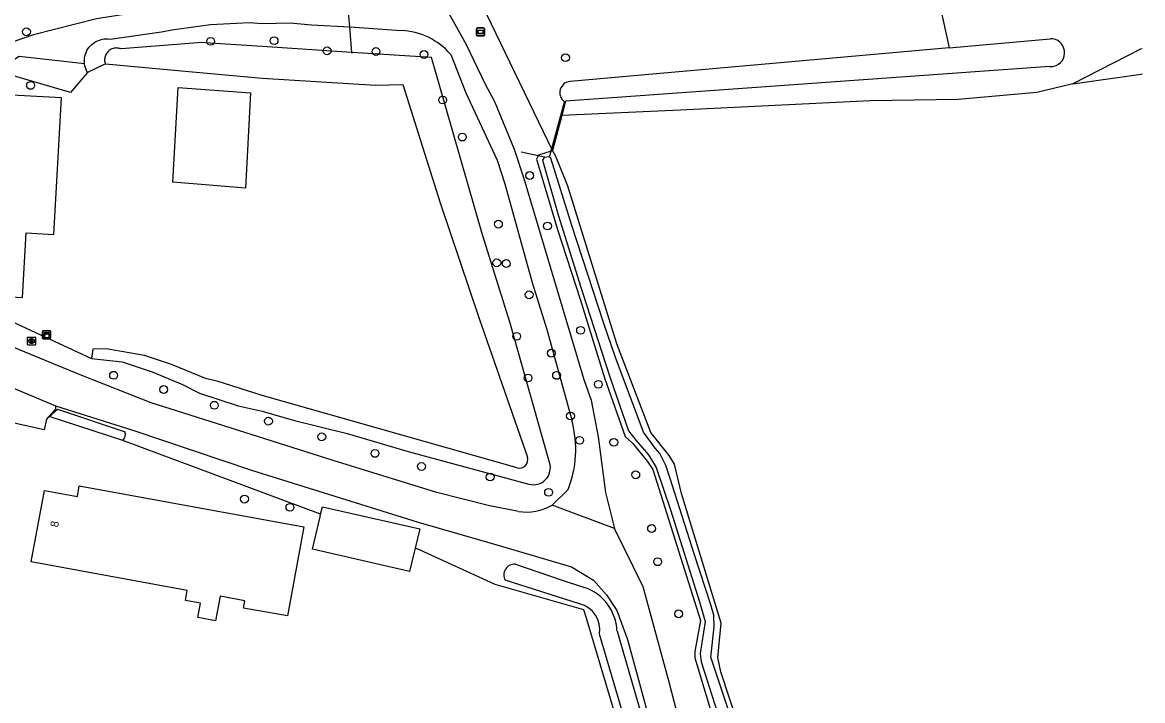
# Model space of a CAD drawing. Extents: x 163863 to 164644, y 379566 to 382155.
# Drawn here: x 164470.1 to 164610, y 381253.7 to 381338.5 of the extents above; entities that cross this region are included whole.
import ezdxf

# ---------------------------------------------------------------- set-up
doc = ezdxf.new("R2010")
doc.units = 0
for name, color, linetype in [('IMGEO_Boom', 7, 'Continuous'), ('IMGEO_Duiker', 7, 'Continuous'), ('IMGEO_Grasland_agrarisch', 7, 'Continuous'), ('IMGEO_Grasland_overig', 7, 'Continuous'), ('IMGEO_Groenvoorziening', 7, 'Continuous'), ('IMGEO_Houtwal', 7, 'Continuous'), ('IMGEO_Kast', 7, 'Continuous'), ('IMGEO_Pand', 7, 'Continuous'), ('IMGEO_Pand_nummerreeks', 7, 'Continuous'), ('IMGEO_Rijbaan_lokaal_onverhard', 7, 'Continuous'), ('IMGEO_Rijbaan_lokaal_open', 7, 'Continuous'), ('IMGEO_Rioolput', 7, 'Continuous'), ('IMGEO_Sloot', 7, 'Continuous'), ('IMGEO_Verklikker', 7, 'Continuous'), ('IMGEO_Waterloop', 7, 'Continuous')]:
    doc.layers.add(name, color=color, linetype=linetype)

msp = doc.modelspace()

# ---------------------------------------------------------------- linework, layer by layer
at = {"layer": 'IMGEO_Boom'}
for centre in [(164470.56, 381337.3), (164493.58, 381336.1), (164501.5, 381336.19), (164508.13, 381334.92), (164514.23, 381334.83), (164520.24, 381334.47), (164537.91, 381334.06), (164471.08, 381330.6), (164522.56, 381328.77), (164525.03, 381324.14), (164533.43, 381319.34), (164529.53, 381313.26), (164535.67, 381313.03), (164529.33, 381308.42), (164530.51, 381308.33), (164533.37, 381304.43), (164539.8, 381299.98), (164531.81, 381299.24), (164536.15, 381297.13), (164481.45, 381294.37), (164536.8, 381294.35), (164533.23, 381294.02), (164542.02, 381293.24), (164487.7, 381292.59), (164494.03, 381290.62), (164500.8, 381288.63), (164538.54, 381289.27), (164507.46, 381286.68), (164539.69, 381286.24), (164543.95, 381285.98), (164514.11, 381284.6), (164519.92, 381282.97), (164528.5, 381281.65), (164546.69, 381281.93), (164497.8, 381278.89), (164535.8, 381279.73), (164503.48, 381277.86), (164548.67, 381275.21), (164549.43, 381271.06), (164552.05, 381264.55)]:
    msp.add_circle(centre, 0.489, dxfattribs=at)
at = {"layer": 'IMGEO_Duiker'}
for points in [[(164511.24, 381334.6), (164511.23, 381334.72), (164510.95, 381337.93), (164510.59, 381341.96), (164510.51, 381342.79), (164510.45, 381343.54), (164510.38, 381344.3)], [(164535.97, 381321.79), (164537.82, 381328.65)], [(164535.29, 381321.62), (164532.37, 381322.25)]]:
    msp.add_lwpolyline(points, dxfattribs=at)
at = {"layer": 'IMGEO_Grasland_agrarisch'}
msp.add_lwpolyline([(164576.41, 381211.1), (164573.23, 381215.26), (164570.32, 381220.27), (164568.53, 381224.27), (164563.46, 381238.67), (164557.34, 381257.3), (164556.93, 381259.1), (164557.37, 381263.39), (164552.4, 381279.61), (164551.54, 381283.27), (164550.85, 381284.34), (164548.58, 381287.22), (164544.33, 381298.3), (164538.21, 381318.01), (164536.75, 381321.62), (164536.3, 381322.47)], dxfattribs=at)
at = {"layer": 'IMGEO_Grasland_overig'}
for points in [[(164536.3, 381322.47), (164528.1, 381339.46)], [(164478.19, 381332.23), (164478.12, 381332.35), (164478.02, 381332.57), (164477.93, 381332.8), (164477.86, 381333.04), (164477.82, 381333.28), (164477.81, 381333.35)], [(164478.19, 381332.23), (164476.06, 381329.71), (164468.34, 381331.96), (164465.28, 381331.44)], [(164601.31, 381330.81), (164609.81, 381332), (164610.02, 381332.03)], [(164537.45, 381326.82), (164536.3, 381322.47)]]:
    msp.add_lwpolyline(points, dxfattribs=at)
at = {"layer": 'IMGEO_Groenvoorziening'}
for points in [[(164480.42, 381333.29), (164478.19, 381332.23)], [(164536.3, 381322.47), (164536.11, 381322.4), (164534.55, 381321.89), (164534.29, 381321.38), (164536.91, 381312.6), (164539.75, 381303.88), (164542.82, 381293.93), (164545.36, 381286.71), (164546.33, 381285.83), (164548.13, 381283.64), (164548.81, 381282.59), (164554.8, 381263.71), (164554.09, 381259.85), (164554.07, 381259.03), (164556.78, 381250.03), (164560.31, 381239.18), (164562.03, 381233.31), (164564.38, 381226.73), (164567.04, 381220.38), (164568.5, 381217.9), (164571.91, 381212.76), (164574.18, 381209.58), (164576.04, 381208.08), (164579.48, 381206.15)], [(164461.17, 381304.57), (164478.7, 381296.48)], [(164473.39, 381289.21), (164473.36, 381289.22)], [(164507.32, 381276.99), (164482.61, 381286.22)], [(164556.3, 381213.51), (164555.39, 381215.78), (164555.19, 381216.36), (164547.24, 381240.23), (164545.64, 381243.44), (164546.57, 381243.66), (164544.69, 381250), (164540.48, 381264.15), (164540.22, 381265.04), (164529.13, 381268.21), (164519.66, 381272.56), (164519.13, 381272.75)]]:
    msp.add_lwpolyline(points, dxfattribs=at)
at = {"layer": 'IMGEO_Houtwal'}
for points in [[(164584.71, 381340.41), (164585.83, 381335.31)], [(164609.96, 381335.18), (164609.75, 381335.12), (164601.31, 381330.81)], [(164601.31, 381330.81), (164596.82, 381329.72), (164586.98, 381328.83), (164575.98, 381328.66), (164552.22, 381327.5), (164537.45, 381326.82)], [(164537.92, 381328.61), (164537.45, 381326.82)]]:
    msp.add_lwpolyline(points, dxfattribs=at)
at = {"layer": 'IMGEO_Kast'}
for p, q in [((164472.58, 381299.01), (164472.58, 381299.85)), ((164472.58, 381299.85), (164472.58, 381299.01)), ((164472.65, 381299.93), (164473.49, 381299.93)), ((164473.49, 381299.93), (164472.65, 381299.93)), ((164473.5, 381298.93), (164472.66, 381298.93)), ((164472.66, 381298.93), (164473.5, 381298.93)), ((164473.58, 381299.86), (164473.58, 381299.02)), ((164473.58, 381299.02), (164473.58, 381299.86))]:
    msp.add_line(p, q, dxfattribs=at)
for points in [[(164472.77, 381299.72), (164473.37, 381299.72), (164473.37, 381299.64), (164472.77, 381299.64), (164472.77, 381299.72)], [(164472.77, 381299.55), (164473.37, 381299.55), (164473.37, 381299.06), (164472.77, 381299.06), (164472.77, 381299.55)]]:
    msp.add_lwpolyline(points, dxfattribs=at)
msp.add_circle((164472.86, 381299.4), 0.0377, dxfattribs=at)
for centre, start, end in [((164472.66, 381299.86), 92.4484, 184.2845), ((164472.66, 381299.86), 92.4484, 184.2845), ((164472.66, 381299.01), 182.4484, 274.2845), ((164472.66, 381299.01), 182.4484, 274.2845), ((164473.5, 381299.86), 2.4484, 94.2845), ((164473.5, 381299.86), 2.4484, 94.2845), ((164473.5, 381299.01), 272.4484, 4.2845), ((164473.5, 381299.01), 272.4484, 4.2845)]:
    msp.add_arc(centre, 0.0779, start, end, dxfattribs=at)
at = {"layer": 'IMGEO_Pand'}
for points in [[(164461.17, 381304.57), (164470.07, 381304.08), (164470.51, 381312.16), (164473.99, 381311.97), (164474.92, 381329.06), (164462.53, 381329.73)], [(164497.92, 381317.77), (164488.86, 381318.51), (164489.5, 381330.35), (164498.57, 381329.66), (164497.92, 381317.77)], [(164491.96, 381264.09), (164492.29, 381265.89), (164490.43, 381266.23), (164490.66, 381267.46), (164471.17, 381271.03), (164472.81, 381279.98), (164476.92, 381279.23), (164477.16, 381280.54), (164505.21, 381275.41), (164503.18, 381264.31), (164497.68, 381265.27), (164497.85, 381266.18), (164494.75, 381266.75), (164494.19, 381263.68), (164491.96, 381264.09)], [(164507.32, 381276.99), (164507.54, 381277.94), (164519.7, 381275.16), (164519.13, 381272.75)], [(164519.13, 381272.75), (164519.01, 381272.24), (164518.44, 381269.85), (164506.29, 381272.62), (164507.24, 381276.67), (164507.32, 381276.99)]]:
    msp.add_lwpolyline(points, dxfattribs=at)
at = {"layer": 'IMGEO_Rijbaan_lokaal_onverhard'}
for points in [[(164495.77, 381388.57), (164500, 381382.04), (164503.75, 381376.16), (164515.61, 381354.14), (164519.97, 381345.71), (164525.51, 381335.7), (164527.86, 381330.74), (164529.04, 381328.58), (164531.51, 381322.61), (164532.72, 381318.95), (164540.2, 381293.84), (164541.11, 381291.26), (164542, 381286.69), (164542.93, 381279.72), (164544.02, 381275.23)], [(164510.59, 381341.96), (164510.3, 381341.84), (164509.8, 381341.67), (164509.29, 381341.54), (164508.78, 381341.47), (164508.25, 381341.43), (164507.73, 381341.45), (164500, 381340.97), (164487.33, 381340.19), (164479.32, 381338.91), (164471.46, 381336.92), (164464.88, 381334.66), (164449.43, 381328.52), (164449.13, 381328.41), (164448.56, 381328.25), (164447.99, 381328.15), (164447.4, 381328.1), (164446.81, 381328.1), (164446.23, 381328.15), (164445.65, 381328.25), (164445.09, 381328.41), (164444.54, 381328.61), (164444.01, 381328.87), (164443.5, 381329.17)], [(164477.81, 381333.35), (164477.8, 381333.53), (164477.8, 381333.77), (164477.82, 381334.02), (164477.86, 381334.26), (164477.93, 381334.5), (164478.01, 381334.73), (164478.12, 381334.95), (164478.25, 381335.16), (164478.39, 381335.36), (164478.55, 381335.55), (164478.73, 381335.72), (164478.92, 381335.87), (164479.12, 381336.01), (164479.34, 381336.13), (164479.57, 381336.23), (164479.8, 381336.3), (164480.04, 381336.36), (164480.28, 381336.4), (164480.53, 381336.41), (164480.78, 381336.4), (164481.02, 381336.37), (164487.43, 381337.28), (164488.73, 381337.54), (164493.57, 381338.22), (164498.45, 381338.47), (164500, 381338.33), (164503.52, 381338.44), (164506.16, 381338.16), (164510.95, 381337.93), (164517.38, 381337.48)], [(164465.28, 381331.44), (164469.66, 381334.24), (164477.81, 381333.35)], [(164523.57, 381334.47), (164525.48, 381329.66), (164529.38, 381321.24), (164530.34, 381318.29), (164533.74, 381305.97), (164535.57, 381300.09), (164538.73, 381288.63)], [(164532.04, 381277.33), (164528.23, 381278.11), (164521.82, 381279.71), (164508.89, 381283.7), (164495.22, 381288.05), (164486.16, 381290.94), (164477.26, 381294.42), (164466.11, 381299), (164450.93, 381304.74), (164445.36, 381306.97), (164444.17, 381307.54)], [(164474.21, 381290.55), (164483.96, 381287.46), (164498.67, 381282.49), (164519.5, 381276.01), (164529.34, 381273.18), (164538.66, 381270.43), (164541.43, 381268.75), (164543.02, 381266.93), (164544.34, 381264.96), (164545.66, 381261.33), (164549.08, 381248.8), (164552.47, 381236.46), (164555.63, 381227.65), (164557.99, 381221.41), (164558.81, 381219.82), (164559.36, 381217.23), (164559.22, 381215.24)], [(164538.24, 381280.07), (164536.24, 381278.12)], [(164544.02, 381275.23), (164536.24, 381278.12)], [(164579.11, 381204.6), (164574.56, 381207.73), (164570.59, 381210.11), (164567.68, 381212.22), (164565.32, 381215.07), (164562.87, 381219.96), (164558.43, 381230.39), (164555.47, 381238.84), (164553.72, 381244.89), (164550.85, 381256.01), (164547.6, 381267.91), (164544.02, 381275.23)]]:
    msp.add_lwpolyline(points, dxfattribs=at)
for centre, radius, start, end in [((164517, 381328.82), 8.66, 40.6544, 87.4808), ((164525.53, 381285.1), 13.66, 338.4212, 14.9848), ((164532.99, 381283.82), 6.55, 261.6407, 299.7286)]:
    msp.add_arc(centre, radius, start, end, dxfattribs=at)
at = {"layer": 'IMGEO_Rijbaan_lokaal_open'}
for points in [[(164467.84, 381292.68), (164467.86, 381292.65), (164468.37, 381293.01), (164474.21, 381290.55)], [(164473.36, 381289.22), (164473.05, 381288.89), (164472.77, 381287.54), (164467.73, 381288.69), (164467.97, 381290.2), (164467.94, 381291.26)], [(164474.21, 381290.55), (164474.18, 381290.13), (164473.36, 381289.22)]]:
    msp.add_lwpolyline(points, dxfattribs=at)
at = {"layer": 'IMGEO_Rioolput'}
for p, q in [((164470.71, 381298.23), (164470.71, 381299.08)), ((164470.78, 381299.15), (164471.63, 381299.15)), ((164471.19, 381298.93), (164471.22, 381298.93)), ((164471.71, 381299.08), (164471.71, 381298.23)), ((164471.63, 381298.15), (164470.78, 381298.15)), ((164471.22, 381298.37), (164471.19, 381298.37))]:
    msp.add_line(p, q, dxfattribs=at)
for points in [[(164470.71, 381298.23), (164470.71, 381299.08)], [(164470.78, 381299.15), (164471.63, 381299.15)], [(164471.29, 381298.85), (164471.04, 381298.85), (164471.04, 381298.45)], [(164471.22, 381298.77), (164471.17, 381298.77), (164471.17, 381298.69)], [(164471.71, 381299.08), (164471.71, 381298.23)], [(164471.63, 381298.15), (164470.78, 381298.15)], [(164471.04, 381298.45), (164471.17, 381298.45), (164471.17, 381298.62), (164471.18, 381298.62)], [(164471.17, 381298.69), (164471.22, 381298.69)], [(164471.22, 381298.59), (164471.3, 381298.45), (164471.43, 381298.45), (164471.37, 381298.58)]]:
    msp.add_lwpolyline(points, dxfattribs=at)
for centre, radius, start, end in [((164470.78, 381299.08), 0.0765, 91.552, 178.448), ((164470.78, 381299.08), 0.0765, 91.552, 178.448), ((164471.23, 381298.68), 0.0964, 77.0061, 93.1865), ((164471.24, 381298.73), 0.0378, 276.6634, 79.6772), ((164471.29, 381298.74), 0.109, 350.3612, 89.416), ((164471.29, 381298.74), 0.112, 277.5842, 350.9817), ((164471.63, 381299.08), 0.0765, 1.552, 88.448), ((164471.63, 381299.08), 0.0765, 1.552, 88.448), ((164470.78, 381298.23), 0.0765, 181.552, 268.448), ((164470.78, 381298.23), 0.0765, 181.552, 268.448), ((164471.18, 381298.56), 0.0533, 26.0293, 88.6989), ((164471.2, 381298.88), 0.19, 274.7715, 282.9687), ((164471.28, 381298.53), 0.108, 29.5134, 73.7905), ((164471.63, 381298.23), 0.0765, 271.552, 358.448), ((164471.63, 381298.23), 0.0765, 271.552, 358.448)]:
    msp.add_arc(centre, radius, start, end, dxfattribs=at)
for centre, major_axis, ratio, start_param, end_param in [((164471.19, 381298.65), (-0.387, 0.002), 0.722429, 4.712389, 7.853982), ((164471.22, 381298.65), (-0.39, 0.002), 0.717154, 1.570796, 4.712389)]:
    msp.add_ellipse(centre, major_axis=major_axis, ratio=ratio, start_param=start_param, end_param=end_param, dxfattribs=at)
at = {"layer": 'IMGEO_Sloot'}
msp.add_lwpolyline([(164560.56, 381245.59), (164556.08, 381259.13), (164556.47, 381262.94), (164556.44, 381264.39), (164556.06, 381265.66), (164554.05, 381271.94), (164550.93, 381281.57), (164550.45, 381283.1), (164549.69, 381284.6), (164549.11, 381285.26), (164547.64, 381287.24), (164544.11, 381296.72), (164542.72, 381300.85), (164538.72, 381313.07), (164536.1, 381321.51), (164535.89, 381321.68), (164535.23, 381321.6), (164535.04, 381321.26), (164536.99, 381314.42), (164540.05, 381304.71), (164543.46, 381294.19), (164545.77, 381287.41), (164546.7, 381286.25), (164548.29, 381284.43), (164549.24, 381282.82), (164551.02, 381277.55), (164554.64, 381266.06), (164555.36, 381263.6), (164554.72, 381259.58), (164554.85, 381258.56), (164558.24, 381248)], dxfattribs=at)
at = {"layer": 'IMGEO_Verklikker'}
for p, q in [((164526.79, 381336.88), (164526.79, 381337.68)), ((164526.79, 381337.68), (164526.79, 381336.88)), ((164526.89, 381337.78), (164527.68, 381337.78)), ((164527.68, 381337.78), (164526.89, 381337.78)), ((164527.68, 381336.78), (164526.89, 381336.78)), ((164526.89, 381336.78), (164527.68, 381336.78)), ((164527.78, 381337.68), (164527.78, 381336.88)), ((164527.78, 381336.88), (164527.78, 381337.68))]:
    msp.add_line(p, q, dxfattribs=at)
for points in [[(164526.89, 381337.51), (164527.68, 381337.51), (164527.68, 381337.05), (164526.89, 381337.05), (164526.89, 381337.51)], [(164526.95, 381337.45), (164526.95, 381337.11), (164527.61, 381337.11), (164527.61, 381337.45), (164526.95, 381337.45)]]:
    msp.add_lwpolyline(points, dxfattribs=at)
for centre, start, end in [((164526.89, 381337.68), 90, 180), ((164526.89, 381337.68), 90, 180), ((164526.89, 381336.88), 180, 270), ((164526.89, 381336.88), 180, 270), ((164527.68, 381337.68), 0, 90), ((164527.68, 381337.68), 360, 90), ((164527.68, 381336.88), 270, 0), ((164527.68, 381336.88), 270, 0)]:
    msp.add_arc(centre, 0.1, start, end, dxfattribs=at)
at = {"layer": 'IMGEO_Waterloop'}
for points in [[(164535.92, 381283.45), (164530.99, 381300.89), (164527.55, 381311.94), (164521.15, 381334.07), (164511.23, 381334.72), (164500, 381335.46), (164492.21, 381335.95), (164491.96, 381335.93), (164482.41, 381335.15), (164482.29, 381335.2), (164482.16, 381335.23), (164482.03, 381335.26), (164481.9, 381335.27), (164481.77, 381335.28), (164481.64, 381335.27), (164481.5, 381335.24), (164481.38, 381335.21), (164481.25, 381335.17), (164481.13, 381335.11), (164481.02, 381335.04), (164480.91, 381334.97), (164480.81, 381334.88), (164480.71, 381334.79), (164480.63, 381334.69), (164480.55, 381334.58), (164480.49, 381334.46), (164480.43, 381334.34), (164480.39, 381334.21), (164480.36, 381334.09), (164480.34, 381333.95), (164480.33, 381333.82), (164480.33, 381333.69), (164480.35, 381333.56), (164480.38, 381333.43), (164480.41, 381333.3), (164480.42, 381333.29)], [(164585.83, 381335.31), (164538.48, 381331.09)], [(164585.83, 381335.31), (164598.48, 381336.44)], [(164480.42, 381333.29), (164491.77, 381332.26), (164500, 381331.52), (164514.17, 381330.64), (164517.58, 381330.72), (164522.24, 381315.93), (164527.11, 381301.46), (164533.16, 381284.14)], [(164598.41, 381332.95), (164537.92, 381328.61)], [(164537.74, 381328.6), (164537.92, 381328.61)], [(164531.88, 381282.81), (164500, 381291.84), (164494.41, 381293.63), (164493.06, 381293.94), (164488.67, 381295.71), (164485.3, 381296.85), (164480.52, 381297.66), (164478.84, 381297.61), (164478.7, 381296.48)], [(164478.7, 381296.48), (164482.51, 381296.05), (164486.26, 381294.81), (164490.07, 381293.22), (164492.17, 381292.13), (164497.01, 381290.56), (164500, 381289.89), (164503.88, 381288.77), (164510.63, 381287.11), (164518.25, 381284.86), (164533.35, 381280.76)], [(164473.39, 381289.21), (164474.43, 381290.12), (164482.88, 381287.29)], [(164482.61, 381286.22), (164473.39, 381289.21)], [(164531.65, 381270.74), (164537.38, 381268.81), (164540.3, 381267.83)], [(164539.67, 381265.79), (164530.39, 381268.77)], [(164544.35, 381262.41), (164544.61, 381261.49), (164547.93, 381250), (164554.87, 381225.96), (164557.19, 381216.3), (164556.08, 381215.89), (164553.07, 381225.44), (164545.72, 381250)], [(164545.72, 381250), (164542.18, 381262.02)]]:
    msp.add_lwpolyline(points, dxfattribs=at)
for centre, radius, start, end in [((164598.54, 381334.69), 1.74, 282.5456, 91.8394), ((164598.54, 381334.68), 1.73, 265.8131, 282.5843), ((164538.6, 381329.7), 1.4, 94.7737, 232.3379), ((164481.86, 381286.98), 1.06, 314.7286, 17.3501), ((164532.17, 381283.81), 1.04, 254.0114, 18.1006), ((164533.9, 381282.8), 2.12, 254.882, 17.7986), ((164531.52, 381269.44), 1.31, 84.1793, 210.6611), ((164538.44, 381262.22), 5.91, 1.8256, 71.6465), ((164538.88, 381262.54), 3.34, 350.9797, 76.274)]:
    msp.add_arc(centre, radius, start, end, dxfattribs=at)

# ---------------------------------------------------------------- texts
at = {"layer": 'IMGEO_Pand_nummerreeks'}
msp.add_text('8', height=1, rotation=79.6297, dxfattribs=at).set_placement((164474.5, 381275.32))

doc.saveas('drawing.dxf')
